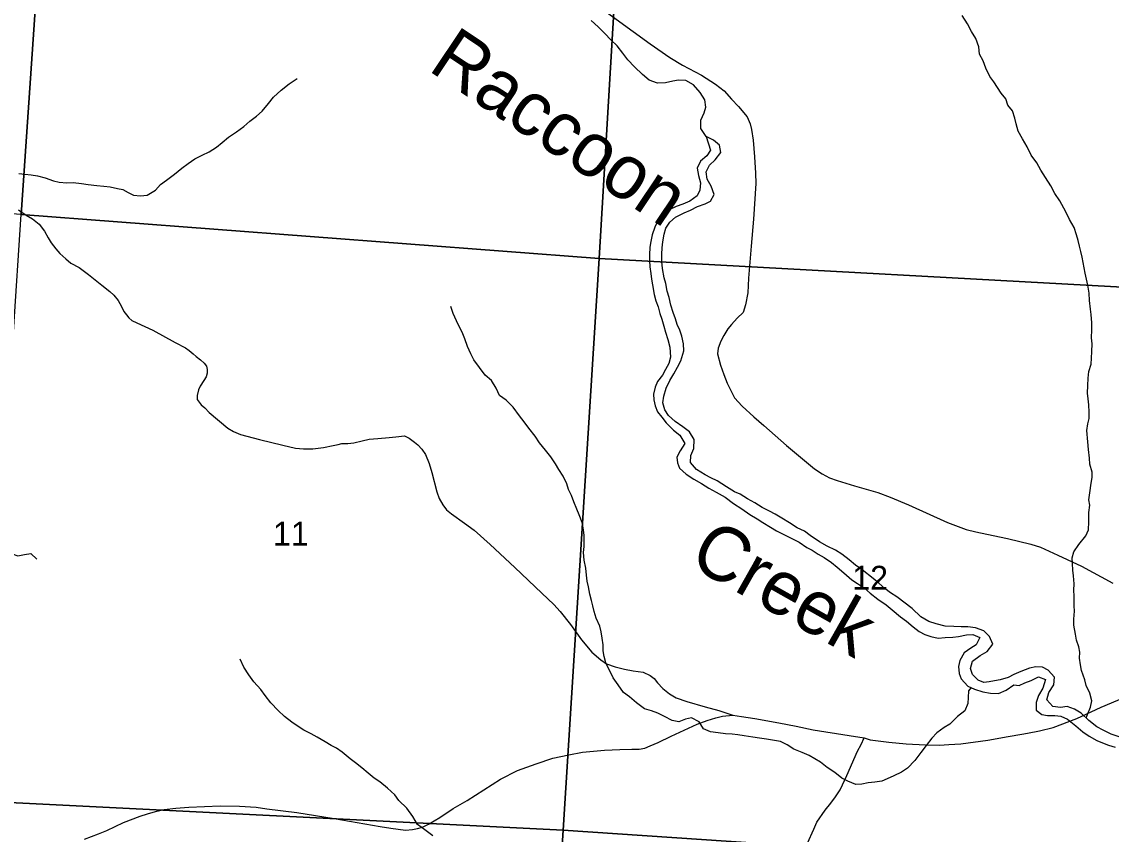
# Model space of a CAD drawing. Extents: x 0 to 34, y 0 to 22.
# Drawn here: x 3.309 to 5.215, y 16.998 to 18.42 of the extents above; entities that cross this region are included whole.
import ezdxf

# ---------------------------------------------------------------- set-up
doc = ezdxf.new("R2010")
doc.units = 0
for name, color, linetype in [('GM_X_Major_River', 7, 'Continuous'), ('GM_X_Major_River_Text', 7, 'Continuous'), ('GM_X_Minor_River', 7, 'Continuous'), ('GM_X_Section', 7, 'Continuous'), ('GM_X_Section_Text', 7, 'Continuous'), ('GM_X_State_Route', 7, 'Continuous'), ('GM_X_Township_Road', 7, 'Continuous')]:
    doc.layers.add(name, color=color, linetype=linetype)

msp = doc.modelspace()

# ---------------------------------------------------------------- linework, layer by layer
at = {"layer": 'GM_X_Major_River'}
for points in [[(4.5062, 18.2191), (4.4968, 18.2332), (4.4969, 18.2476), (4.5023, 18.2605), (4.5054, 18.2703), (4.5035, 18.2832), (4.4957, 18.2958), (4.484, 18.3092), (4.4704, 18.3169), (4.4575, 18.3177), (4.4476, 18.3155), (4.4347, 18.3129), (4.4211, 18.3123), (4.4063, 18.3177), (4.3946, 18.3277), (4.3807, 18.3407), (4.369, 18.3533), (4.3603, 18.3647), (4.3506, 18.3777), (4.3392, 18.3884), (4.3287, 18.3991), (4.317, 18.4106), (4.305, 18.422)], [(5.0108, 17.2661), (5.0013, 17.2643), (4.9918, 17.2636), (4.982, 17.2675), (4.9722, 17.2774), (4.9688, 17.2877), (4.972, 17.3005), (4.9853, 17.3107), (4.9979, 17.3178), (5.0074, 17.3302), (5.0018, 17.3436), (4.9917, 17.3539), (4.9773, 17.3589), (4.964, 17.3609), (4.9523, 17.361), (4.9394, 17.3615), (4.9242, 17.362), (4.9083, 17.3659), (4.8958, 17.3702), (4.8818, 17.3782), (4.8664, 17.3928), (4.8399, 17.4134), (4.8286, 17.4203), (4.8188, 17.4276), (4.8079, 17.4372), (4.7981, 17.4452), (4.7792, 17.4606), (4.7675, 17.4686), (4.7562, 17.4778), (4.7437, 17.4878), (4.7324, 17.495), (4.718, 17.502), (4.7044, 17.5093), (4.6878, 17.5208), (4.678, 17.5281), (4.6655, 17.5342), (4.6519, 17.5427), (4.6387, 17.5507), (4.627, 17.5577), (4.6171, 17.563), (4.6043, 17.5696), (4.5914, 17.5777), (4.5786, 17.585), (4.5654, 17.593), (4.5555, 17.5973), (4.5419, 17.6061), (4.5253, 17.6165), (4.514, 17.6215), (4.5041, 17.6269), (4.489, 17.6361), (4.4789, 17.6483), (4.479, 17.6608), (4.4843, 17.6729), (4.4852, 17.6885), (4.4766, 17.7018), (4.4653, 17.711), (4.452, 17.7202), (4.4403, 17.7309), (4.434, 17.7404), (4.4303, 17.753), (4.4318, 17.7647), (4.4361, 17.7787), (4.4426, 17.792), (4.4492, 17.8033), (4.4557, 17.815), (4.4618, 17.8264), (4.4669, 17.8438), (4.4666, 17.8563), (4.4636, 17.8696), (4.4599, 17.8799), (4.4551, 17.8902), (4.4521, 17.8997), (4.4484, 17.9107), (4.4443, 17.924), (4.4413, 17.9369), (4.438, 17.9483), (4.4354, 17.9616), (4.4325, 17.9715), (4.4299, 17.9878), (4.4285, 18), (4.4282, 18.0129), (4.429, 18.0239), (4.4302, 18.0345), (4.4326, 18.0481), (4.4353, 18.0584), (4.4426, 18.0693), (4.4521, 18.0776), (4.4673, 18.0855), (4.4784, 18.0899), (4.4909, 18.0963), (4.5042, 18.1011), (4.5138, 18.1056), (4.5203, 18.1177), (4.5147, 18.1318), (4.5076, 18.144), (4.5061, 18.1569), (4.5119, 18.1686), (4.5218, 18.178), (4.5318, 18.1912), (4.5292, 18.2038), (4.519, 18.2125)], [(4.5062, 18.2191), (4.5136, 18.1951), (4.5071, 18.1849)], [(4.519, 18.2125), (4.5062, 18.2191)], [(4.5071, 18.1849), (4.496, 18.1755), (4.4902, 18.1634), (4.4928, 18.1505), (4.4961, 18.1376), (4.4949, 18.1251), (4.4903, 18.1153), (4.4777, 18.1055), (4.4655, 18.1003), (4.4538, 18.0966), (4.4423, 18.0909), (4.4298, 18.0812), (4.421, 18.0699), (4.4164, 18.06), (4.4117, 18.0468), (4.409, 18.0354), (4.4074, 18.0252), (4.4066, 18.0119), (4.4069, 18.0021), (4.4075, 17.9907), (4.409, 17.9793), (4.4101, 17.9694), (4.4119, 17.9591), (4.4152, 17.9424), (4.4182, 17.9314), (4.4219, 17.9207), (4.4252, 17.9093), (4.4286, 17.8991), (4.4319, 17.8869), (4.4349, 17.8766), (4.439, 17.8637), (4.4427, 17.85), (4.4437, 17.8329), (4.4409, 17.8216), (4.4348, 17.811), (4.4294, 17.8012), (4.421, 17.7902), (4.4168, 17.7804), (4.414, 17.7679), (4.4144, 17.758), (4.4169, 17.7478), (4.421, 17.7371), (4.4282, 17.7276), (4.4361, 17.7177), (4.4489, 17.7047), (4.4598, 17.6962), (4.4685, 17.6818), (4.4604, 17.6689), (4.455, 17.6576), (4.4557, 17.6481), (4.4595, 17.6386), (4.4712, 17.6279), (4.4847, 17.619), (4.4976, 17.6114), (4.5108, 17.6037), (4.5237, 17.5967), (4.5392, 17.5875), (4.5539, 17.5768), (4.5682, 17.5672), (4.5826, 17.5572), (4.5954, 17.5499), (4.6053, 17.5434), (4.6189, 17.535), (4.6294, 17.5288), (4.6442, 17.5211), (4.6548, 17.5157), (4.6687, 17.5088), (4.682, 17.4996), (4.6918, 17.495), (4.702, 17.4877), (4.7126, 17.4819), (4.7254, 17.4731), (4.7352, 17.4654), (4.7469, 17.4551), (4.7612, 17.4432), (4.7711, 17.4367), (4.7831, 17.4283), (4.793, 17.4199), (4.8065, 17.4095), (4.8209, 17.3992), (4.8318, 17.3907), (4.8462, 17.3781), (4.8564, 17.3708), (4.8684, 17.3609), (4.879, 17.3528), (4.8888, 17.3474), (4.8994, 17.3436), (4.9119, 17.3412), (4.9241, 17.3422), (4.9377, 17.3429), (4.9476, 17.3436), (4.9613, 17.3465), (4.9726, 17.3472), (4.9848, 17.3422), (4.9786, 17.3293), (4.9691, 17.3237), (4.9573, 17.3151), (4.95, 17.3018), (4.9476, 17.2916), (4.9487, 17.2791), (4.952, 17.2696)], [(5.229, 17.1681), (5.2146, 17.1732), (5.201, 17.1797), (5.1897, 17.1855), (5.1757, 17.197), (5.1621, 17.2096), (5.1508, 17.2169), (5.138, 17.2212), (5.1258, 17.2197), (5.1129, 17.2213), (5.102, 17.2332), (5.1055, 17.2461), (5.1143, 17.2593), (5.1155, 17.2725), (5.1042, 17.2848), (5.0944, 17.2901), (5.0827, 17.2906), (5.0716, 17.2884), (5.0564, 17.2828), (5.0446, 17.2772), (5.0347, 17.2724), (5.0207, 17.2683), (5.0108, 17.2661)], [(4.952, 17.2696), (4.9637, 17.257), (4.9758, 17.2519), (4.9902, 17.2473), (5.0038, 17.2445), (5.0175, 17.2444), (5.0308, 17.25), (5.0445, 17.259), (5.054, 17.2582), (5.0639, 17.2627), (5.0745, 17.2668), (5.0875, 17.2735), (5.1, 17.2685), (5.0953, 17.2537), (5.0876, 17.2405), (5.0834, 17.2284), (5.0833, 17.2147), (5.0935, 17.2071), (5.1033, 17.2059), (5.1162, 17.2058), (5.1265, 17.2045), (5.1386, 17.1991), (5.1529, 17.1873), (5.165, 17.1769), (5.1763, 17.1693), (5.1899, 17.162), (5.1997, 17.1577), (5.2103, 17.1538), (5.2217, 17.1503)]]:
    msp.add_lwpolyline(points, dxfattribs=at)
at = {"layer": 'GM_X_Minor_River'}
for points in [[(5.1711, 17.2013), (5.1735, 17.2075), (5.1788, 17.2201), (5.181, 17.2315), (5.1772, 17.2447), (5.1711, 17.2584), (5.1684, 17.2682), (5.1631, 17.2845), (5.1608, 17.294), (5.1596, 17.3057), (5.1599, 17.3163), (5.158, 17.3258), (5.1542, 17.3372), (5.1523, 17.3482), (5.1492, 17.3637), (5.1495, 17.374), (5.1506, 17.388), (5.1502, 17.3978), (5.1498, 17.4142), (5.1494, 17.4251), (5.1497, 17.4361), (5.1489, 17.4498), (5.1477, 17.4597), (5.1469, 17.4718), (5.1465, 17.4816), (5.1495, 17.4919), (5.1582, 17.5048), (5.1702, 17.52), (5.1751, 17.5306), (5.1758, 17.5447), (5.1758, 17.5606), (5.1773, 17.5735), (5.1757, 17.5833), (5.1772, 17.5955), (5.1798, 17.6122), (5.1816, 17.622), (5.1816, 17.6315), (5.1774, 17.6455), (5.1766, 17.6561), (5.1751, 17.6709), (5.1739, 17.6846), (5.1723, 17.7043), (5.1738, 17.716), (5.176, 17.7255), (5.1764, 17.7362), (5.1756, 17.7494), (5.1744, 17.76), (5.1736, 17.7695), (5.1739, 17.7832), (5.1743, 17.7961), (5.1757, 17.8074), (5.1799, 17.8207), (5.1802, 17.831), (5.1809, 17.8427), (5.1816, 17.856), (5.1805, 17.8666), (5.1808, 17.8806), (5.1808, 17.8931), (5.18, 17.9076), (5.1788, 17.917), (5.1769, 17.9318), (5.1764, 17.9447), (5.1741, 17.9587), (5.1718, 17.969), (5.1695, 17.98), (5.1641, 18.008), (5.1618, 18.0175), (5.1591, 18.0273), (5.1572, 18.0372), (5.1541, 18.0467), (5.1499, 18.0599), (5.1419, 18.0735), (5.137, 18.0838), (5.1317, 18.0936), (5.1248, 18.1061), (5.1164, 18.1194), (5.1092, 18.1326), (5.0997, 18.147), (5.0917, 18.1603), (5.0848, 18.1731), (5.0746, 18.186), (5.0677, 18.2008), (5.0597, 18.2148), (5.0521, 18.2284), (5.0483, 18.2409), (5.0464, 18.2508), (5.0418, 18.264), (5.0342, 18.2739), (5.0304, 18.2848), (5.022, 18.2947), (5.0159, 18.3045), (5.0094, 18.3144), (5.0026, 18.3242), (4.9957, 18.3386), (4.9908, 18.3515), (4.9843, 18.3628), (4.9831, 18.3761), (4.9778, 18.3905), (4.9702, 18.403), (4.9633, 18.4163), (4.9542, 18.4306)], [(3.3251, 18.1517), (3.3361, 18.1499), (3.3493, 18.1465), (3.3641, 18.1416), (3.3739, 18.1393), (3.3872, 18.1379), (3.3986, 18.1383), (3.4129, 18.1368), (3.4247, 18.1349), (3.4398, 18.1331), (3.4519, 18.1319), (3.4629, 18.1308), (3.4758, 18.1282), (3.4853, 18.126), (3.4948, 18.1211), (3.5042, 18.1165), (3.5164, 18.115), (3.5281, 18.1162), (3.5424, 18.125), (3.5511, 18.1348), (3.5617, 18.1424), (3.5757, 18.1531), (3.5885, 18.1634), (3.5994, 18.1717), (3.6115, 18.1797), (3.624, 18.1862), (3.6361, 18.1919), (3.6493, 18.2003), (3.6591, 18.2083), (3.6705, 18.2178), (3.6841, 18.2269), (3.6969, 18.2364), (3.7075, 18.2456), (3.7192, 18.2543), (3.729, 18.2634), (3.7403, 18.2767), (3.749, 18.2878), (3.7626, 18.2999), (3.7765, 18.3113), (3.7901, 18.3205)], [(3.3035, 18.1543), (3.3137, 18.1532), (3.3251, 18.1517)], [(4.1383, 17.7787), (4.1303, 17.792), (4.1196, 17.801), (4.1094, 17.8147), (4.0995, 17.8279), (4.0941, 17.8385), (4.0884, 17.8514), (4.0835, 17.865), (4.0789, 17.8764), (4.0739, 17.8862), (4.069, 17.8965), (4.0636, 17.909), (4.0591, 17.9215)], [(4.9698, 17.2545), (4.9648, 17.2487), (4.9645, 17.2374), (4.9641, 17.2268), (4.9585, 17.2138), (4.946, 17.204), (4.9325, 17.1907), (4.9226, 17.1849), (4.9098, 17.1754), (4.9007, 17.1659), (4.8909, 17.153), (4.8819, 17.1409), (4.871, 17.1268), (4.8585, 17.1135), (4.8476, 17.1063), (4.8347, 17.0998), (4.823, 17.0948), (4.8132, 17.0906), (4.8011, 17.0891), (4.7893, 17.0875), (4.7787, 17.0852), (4.7678, 17.0848), (4.7537, 17.0905), (4.7435, 17.0958), (4.731, 17.106), (4.7177, 17.1147), (4.7063, 17.1241), (4.6964, 17.1298), (4.6862, 17.1358), (4.6741, 17.1411), (4.6597, 17.1468), (4.6475, 17.1543), (4.6362, 17.16), (4.6221, 17.1626), (4.6115, 17.1641), (4.5994, 17.1659), (4.5877, 17.1678), (4.5725, 17.17), (4.5612, 17.1715), (4.5513, 17.1727), (4.5396, 17.1738), (4.5271, 17.1752), (4.5138, 17.1771), (4.5013, 17.1824), (4.4937, 17.1945), (4.4804, 17.2013), (4.4698, 17.1994), (4.4585, 17.1948), (4.4464, 17.197), (4.4331, 17.2038), (4.4217, 17.2099), (4.4104, 17.2136), (4.3979, 17.2174), (4.3842, 17.2276), (4.3717, 17.2382), (4.3614, 17.2461), (4.3519, 17.259), (4.3436, 17.2715), (4.3302, 17.298), (4.3275, 17.3086), (4.326, 17.3188), (4.3256, 17.3295), (4.324, 17.3412), (4.3221, 17.3518), (4.3202, 17.3621), (4.3133, 17.3761), (4.3103, 17.3874), (4.3079, 17.3973), (4.3053, 17.4068), (4.3026, 17.4178), (4.2999, 17.431), (4.298, 17.4409), (4.2964, 17.4515), (4.2956, 17.4632), (4.2925, 17.4776), (4.2914, 17.4909), (4.2925, 17.5015), (4.2928, 17.511), (4.2924, 17.5209), (4.2912, 17.5303), (4.2889, 17.5432), (4.2836, 17.5569), (4.2798, 17.5667), (4.2744, 17.5796), (4.2702, 17.5906), (4.2649, 17.6012), (4.2622, 17.611), (4.2557, 17.6243), (4.2485, 17.6364), (4.2424, 17.6463), (4.2344, 17.6584), (4.2249, 17.6697), (4.2147, 17.683), (4.207, 17.6943), (4.1956, 17.7083), (4.1877, 17.7193), (4.1793, 17.7299), (4.1683, 17.745), (4.1561, 17.7575), (4.1444, 17.7655), (4.1383, 17.7787)], [(3.1736, 17.4586), (3.1873, 17.4605), (3.1971, 17.4628), (3.2099, 17.467), (3.2236, 17.472), (3.2334, 17.4758), (3.2451, 17.4815), (3.2561, 17.485), (3.2693, 17.4884), (3.2814, 17.4899), (3.2916, 17.4885), (3.3015, 17.4851), (3.3132, 17.4874), (3.3242, 17.4889), (3.3348, 17.4795)], [(4.0276, 16.995), (4.0136, 17.0056), (4.0011, 17.0147), (3.9927, 17.0287), (3.9824, 17.0435), (3.9684, 17.0567), (3.9611, 17.0665), (3.9486, 17.0783), (3.9349, 17.0896), (3.9251, 17.096), (3.9148, 17.1047), (3.9038, 17.1142), (3.8924, 17.1229), (3.883, 17.1297), (3.8689, 17.1414), (3.8594, 17.1486), (3.8499, 17.1531), (3.8393, 17.1595), (3.8253, 17.1674), (3.815, 17.1735), (3.8022, 17.1799), (3.7904, 17.1875), (3.7809, 17.1939), (3.768, 17.2041), (3.7574, 17.2143), (3.7445, 17.2279), (3.7342, 17.2408), (3.7266, 17.251), (3.7144, 17.2646), (3.7057, 17.2767), (3.6969, 17.2904), (3.6908, 17.304)]]:
    msp.add_lwpolyline(points, dxfattribs=at)
at = {"layer": 'GM_X_Section'}
for points in [[(2.3543, 19.1806), (2.3838, 19.1776), (3.378, 19.1131), (3.3075, 18.0826), (2.2906, 18.1558)], [(3.378, 19.1131), (3.4007, 19.112), (4.3808, 19.0475), (4.3187, 18.0057), (3.3075, 18.0826)], [(4.3808, 19.0475), (4.4009, 19.0464), (5.4174, 18.9797), (5.3412, 17.9492), (4.3187, 18.0057)], [(4.3187, 18.0057), (4.2561, 17.0047), (3.2396, 17.0555), (3.3075, 18.0826)], [(4.3187, 18.0057), (5.3412, 17.9492), (5.2673, 16.9365), (4.2561, 17.0047)], [(3.2396, 17.0555), (4.2561, 17.0047), (4.189, 15.9719), (3.1721, 16.0496)], [(4.2561, 17.0047), (5.2673, 16.9365), (5.1915, 15.9177), (4.189, 15.9719)]]:
    msp.add_lwpolyline(points, close=True, dxfattribs=at)
at = {"layer": 'GM_X_State_Route'}
msp.add_lwpolyline([(4.6833, 16.982), (4.6942, 17.0068), (4.6999, 17.0192), (4.7141, 17.0397), (4.7241, 17.0522), (4.7323, 17.0634), (4.7405, 17.0755), (4.7523, 17.1008), (4.771, 17.143), (4.7775, 17.1546), (4.7827, 17.1667), (4.7932, 17.1631), (4.8068, 17.1615), (4.8255, 17.1587), (4.8563, 17.156), (4.8897, 17.154), (4.9143, 17.1539), (4.9304, 17.1549), (4.9514, 17.156), (4.9989, 17.1624), (5.0345, 17.1686), (5.0582, 17.1727), (5.0684, 17.1747), (5.0892, 17.1788), (5.1131, 17.1847), (5.1544, 17.2005), (5.1972, 17.2203), (5.2376, 17.2374)], dxfattribs=at)
at = {"layer": 'GM_X_Township_Road'}
for points in [[(4.3123, 18.4507), (4.4078, 18.3814), (4.4423, 18.357), (4.4648, 18.3439), (4.4977, 18.326), (4.5223, 18.3106), (4.5373, 18.2986), (4.5506, 18.2843), (4.5628, 18.2712), (4.5775, 18.2531), (4.5828, 18.2409), (4.5854, 18.231), (4.5884, 18.2126), (4.5909, 18.1835), (4.5925, 18.1548), (4.5927, 18.1369), (4.5886, 18.0745), (4.5849, 18.0272), (4.5801, 17.9708), (4.5789, 17.9453), (4.575, 17.9246), (4.5709, 17.9108), (4.5605, 17.9011), (4.5504, 17.8901), (4.544, 17.8821), (4.5371, 17.8707), (4.5318, 17.8608), (4.5269, 17.8486), (4.5261, 17.8383), (4.531, 17.8187), (4.5371, 17.8027), (4.5428, 17.7872), (4.5502, 17.7718), (4.5559, 17.7615), (4.569, 17.7467), (4.5895, 17.7283), (4.6072, 17.7129), (4.6465, 17.6784), (4.6955, 17.6375), (4.7088, 17.6288), (4.7217, 17.6218), (4.735, 17.6168), (4.7654, 17.6075), (4.8062, 17.5959), (4.8279, 17.5878), (4.86, 17.5743), (4.9281, 17.5433), (4.9612, 17.5314), (4.9777, 17.5272), (5.0081, 17.5207), (5.0335, 17.5152), (5.0742, 17.5054), (5.0911, 17.5002), (5.1216, 17.4864), (5.163, 17.467), (5.2175, 17.4373)], [(3.303, 18.0907), (3.3159, 18.0812), (3.3272, 18.0748), (3.3332, 18.0703), (3.3388, 18.0653), (3.3481, 18.0532), (3.3549, 18.0416), (3.3602, 18.0327), (3.3678, 18.0222), (3.3751, 18.014), (3.3853, 18.0047), (3.3945, 17.9973), (3.4087, 17.9895), (3.4255, 17.9777), (3.4487, 17.9588), (3.4623, 17.9478), (3.4696, 17.9414), (3.477, 17.9317), (3.4829, 17.9216), (3.4871, 17.9126), (3.4917, 17.9066), (3.4961, 17.9017), (3.5009, 17.8971), (3.5099, 17.8926), (3.5381, 17.8798), (3.5771, 17.8585), (3.5951, 17.8488), (3.6016, 17.8445), (3.6084, 17.8386), (3.6137, 17.8337), (3.6215, 17.828), (3.6278, 17.822), (3.6316, 17.8168), (3.633, 17.8112), (3.6328, 17.805), (3.6311, 17.7983), (3.6271, 17.7922), (3.6207, 17.7822), (3.6176, 17.7756), (3.6153, 17.7659), (3.6151, 17.7586), (3.6226, 17.7496), (3.6286, 17.7441), (3.6366, 17.736), (3.6693, 17.7084), (3.679, 17.7027), (3.6914, 17.6974), (3.7247, 17.6884), (3.7652, 17.6787), (3.7875, 17.6735), (3.8012, 17.6723), (3.8178, 17.6726), (3.8366, 17.6745), (3.8532, 17.678), (3.8619, 17.6801), (3.8683, 17.6814), (3.8789, 17.6814), (3.8894, 17.683), (3.9039, 17.6861), (3.9161, 17.6894), (3.9316, 17.6906), (3.9514, 17.6924), (3.9631, 17.6932), (3.9784, 17.6949), (3.9865, 17.6908), (3.9957, 17.684), (4.0015, 17.6794), (4.0086, 17.6716), (4.0147, 17.6622), (4.0214, 17.6467), (4.0261, 17.6311), (4.0346, 17.5968), (4.0391, 17.5854), (4.0452, 17.5742), (4.0516, 17.5657), (4.0604, 17.5584), (4.0834, 17.5425), (4.1, 17.53), (4.1282, 17.5048), (4.171, 17.4648), (4.2184, 17.4195), (4.2395, 17.4001), (4.2504, 17.3876), (4.2684, 17.3649), (4.2878, 17.3379), (4.3058, 17.3165), (4.3217, 17.3028), (4.3317, 17.2961), (4.3468, 17.2905), (4.3632, 17.2867), (4.3786, 17.2838), (4.3956, 17.2814), (4.4082, 17.2758), (4.4153, 17.2706), (4.421, 17.263), (4.4304, 17.2526), (4.4418, 17.2433), (4.4537, 17.2365), (4.4722, 17.2303), (4.5044, 17.2206), (4.528, 17.2142), (4.5528, 17.2064)], [(3.4181, 16.9893), (3.4427, 16.9984), (3.4571, 17.0044), (3.4863, 17.0182), (3.5157, 17.0297), (3.5287, 17.0333), (3.5424, 17.0374), (3.5579, 17.0411), (3.5779, 17.0436), (3.6007, 17.0454), (3.6555, 17.0477), (3.6897, 17.047), (3.7189, 17.0449), (3.7371, 17.0424), (3.79, 17.0356), (3.8553, 17.0253), (3.9357, 17.0112), (3.954, 17.0082), (3.9798, 17.0051), (3.9921, 17.0059), (4.0008, 17.0078), (4.0099, 17.0104), (4.0199, 17.0157), (4.04, 17.0271), (4.0635, 17.0431), (4.088, 17.0571), (4.146, 17.0944), (4.1759, 17.1092), (4.2087, 17.1213), (4.2377, 17.1307), (4.2659, 17.1368), (4.2899, 17.1414), (4.328, 17.1448), (4.3549, 17.1459), (4.3759, 17.1466), (4.3887, 17.1466), (4.3989, 17.1485), (4.408, 17.1523), (4.4219, 17.1585), (4.4447, 17.1695), (4.4903, 17.1906), (4.5077, 17.1968), (4.523, 17.2018), (4.5348, 17.2044), (4.5528, 17.2064), (4.5676, 17.2037), (4.5914, 17.2005), (4.6331, 17.1927), (4.6633, 17.1867)], [(4.6633, 17.1867), (4.6935, 17.1808), (4.7565, 17.1708), (4.7827, 17.1667)]]:
    msp.add_lwpolyline(points, dxfattribs=at)

# ---------------------------------------------------------------- texts
at = {"layer": 'GM_X_Major_River_Text'}
for s, rotation, p in [('Raccoon', 326.2028, (4.0173, 18.3359)), ('Creek', 330.5751, (4.4724, 17.4705))]:
    msp.add_text(s, height=0.0947, rotation=rotation, dxfattribs=at).set_placement(p)
at = {"layer": 'GM_X_Section_Text'}
for s, p in [('11', (3.7481, 17.5029)), ('12', (4.7619, 17.4257))]:
    msp.add_text(s, height=0.04186, rotation=0, dxfattribs=at).set_placement(p)

doc.saveas('drawing.dxf')
